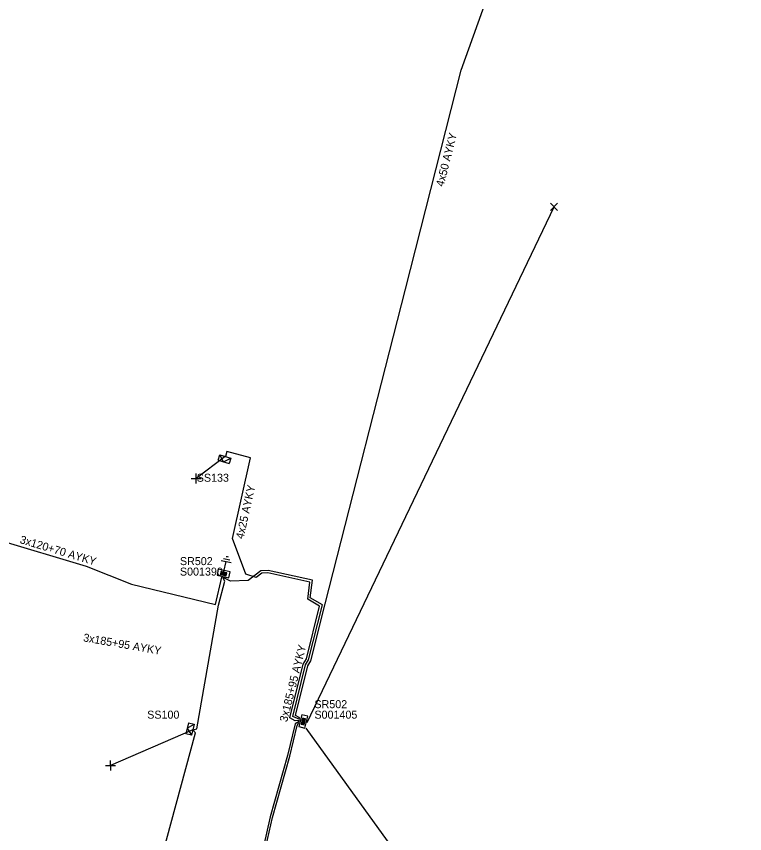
# Model space of a CAD drawing. Extents: x -762500 to -761285, y -1155006 to -1154135.
# Drawn here: x -761930.7 to -761840.3, y -1154545.1 to -1154443.6 of the extents above; entities that cross this region are included whole.
import ezdxf

# ---------------------------------------------------------------- set-up
doc = ezdxf.new("R2010")
doc.units = 0
for name, color, linetype in [('Vrstva 15', 7, 'Continuous'), ('Vrstva 28', 7, 'Continuous'), ('Vrstva 29', 7, 'Continuous'), ('Vrstva 30', 7, 'Continuous'), ('Vrstva 31', 7, 'Continuous'), ('Vrstva 33', 7, 'Continuous'), ('Vrstva 34', 7, 'Continuous'), ('Vrstva 5', 7, 'Continuous'), ('Vrstva 59', 7, 'Continuous'), ('Vrstva 6', 7, 'Continuous')]:
    doc.layers.add(name, color=color, linetype=linetype)

msp = doc.modelspace()

# ---------------------------------------------------------------- linework, layer by layer
at = {"layer": 'Vrstva 15'}
for points in [[(-761904.983, -1154510.928), (-761904.212, -1154511.091)], [(-761904.672, -1154510.672), (-761904.542, -1154510.699)], [(-761904.542, -1154510.699), (-761904.417, -1154510.726)], [(-761905.283, -1154511.181), (-761904.06, -1154511.441)], [(-761904.932, -1154512.533), (-761904.672, -1154511.311)]]:
    msp.add_lwpolyline(points, dxfattribs=at)
at = {"layer": 'Vrstva 28'}
for points in [[(-761905.64, -1154512.273), (-761905.796, -1154513.007)], [(-761905.796, -1154513.007), (-761904.329, -1154513.319)], [(-761904.173, -1154512.585), (-761905.64, -1154512.273)], [(-761905.304, -1154512.538), (-761905.383, -1154512.907)], [(-761905.383, -1154512.907), (-761904.655, -1154513.062)], [(-761905.268, -1154512.594), (-761905.327, -1154512.871)], [(-761905.327, -1154512.871), (-761904.691, -1154513.006)], [(-761904.576, -1154512.693), (-761905.304, -1154512.538)], [(-761905.231, -1154512.65), (-761905.271, -1154512.835)], [(-761905.271, -1154512.835), (-761904.728, -1154512.95)], [(-761904.632, -1154512.729), (-761905.268, -1154512.594)], [(-761904.688, -1154512.765), (-761905.231, -1154512.65)], [(-761905.195, -1154512.706), (-761905.215, -1154512.798)], [(-761905.215, -1154512.798), (-761904.764, -1154512.894)], [(-761904.744, -1154512.802), (-761905.195, -1154512.706)], [(-761904.795, -1154512.839), (-761905.164, -1154512.761)], [(-761904.764, -1154512.894), (-761904.744, -1154512.802)], [(-761904.728, -1154512.95), (-761904.688, -1154512.765)], [(-761904.691, -1154513.006), (-761904.632, -1154512.729)], [(-761904.655, -1154513.062), (-761904.576, -1154512.693)], [(-761904.329, -1154513.319), (-761904.173, -1154512.585)], [(-761895.272, -1154530.34), (-761895.635, -1154531.795)], [(-761895.187, -1154530.756), (-761895.367, -1154531.479)], [(-761895.152, -1154530.814), (-761895.31, -1154531.444)], [(-761894.544, -1154530.521), (-761895.272, -1154530.34)], [(-761895.118, -1154530.871), (-761895.252, -1154531.41)], [(-761895.084, -1154530.928), (-761895.195, -1154531.375)], [(-761894.82, -1154530.848), (-761895.187, -1154530.756)], [(-761894.877, -1154530.882), (-761895.152, -1154530.814)], [(-761895.139, -1154531.347), (-761895.048, -1154530.98)], [(-761894.935, -1154530.917), (-761895.118, -1154530.871)], [(-761895.103, -1154531.398), (-761894.992, -1154530.951)], [(-761894.992, -1154530.951), (-761895.084, -1154530.928)], [(-761895.069, -1154531.455), (-761894.935, -1154530.917)], [(-761895.035, -1154531.513), (-761894.877, -1154530.882)], [(-761895, -1154531.57), (-761894.82, -1154530.848)], [(-761894.907, -1154531.977), (-761894.544, -1154530.521)], [(-761895.635, -1154531.795), (-761894.907, -1154531.977)], [(-761895.367, -1154531.479), (-761895, -1154531.57)], [(-761895.31, -1154531.444), (-761895.035, -1154531.513)], [(-761895.252, -1154531.41), (-761895.069, -1154531.455)], [(-761895.195, -1154531.375), (-761895.103, -1154531.398)]]:
    msp.add_lwpolyline(points, dxfattribs=at)
at = {"layer": 'Vrstva 31'}
for points in [[(-761905.647, -1154498.735), (-761905.442, -1154498.065), (-761904.104, -1154498.475), (-761904.308, -1154499.144)], [(-761905.647, -1154498.735), (-761904.308, -1154499.144)], [(-761904.978, -1154498.939), (-761905.442, -1154498.065)], [(-761904.978, -1154498.939), (-761904.104, -1154498.475)], [(-761909.319, -1154531.329), (-761909.658, -1154532.687)], [(-761909.319, -1154531.329), (-761908.64, -1154531.498), (-761908.979, -1154532.856), (-761909.658, -1154532.687)], [(-761909.488, -1154532.008), (-761908.64, -1154531.498)], [(-761909.488, -1154532.008), (-761908.979, -1154532.856)]]:
    msp.add_lwpolyline(points, dxfattribs=at)
at = {"layer": 'Vrstva 34'}
for points in [[(-761864.422, -1154466.828), (-761863.538, -1154467.712)], [(-761864.422, -1154467.712), (-761863.538, -1154466.828)], [(-761908.369, -1154501.625), (-761908.391, -1154500.375)], [(-761909.005, -1154501.011), (-761907.755, -1154500.989)], [(-761918.989, -1154537.255), (-761919.011, -1154536.005)], [(-761919.625, -1154536.641), (-761918.375, -1154536.619)]]:
    msp.add_lwpolyline(points, dxfattribs=at)
at = {"layer": 'Vrstva 5'}
for points in [[(-761895.51, -1154530.78), (-761895.62, -1154530.65), (-761896.05, -1154530.41), (-761894.54, -1154524.27), (-761894.15, -1154523.62), (-761892.39, -1154516.56), (-761882.4, -1154477.51), (-761875.49, -1154450.3), (-761869.77, -1154434.24), (-761865.39, -1154418.93), (-761865.76, -1154418.41)], [(-761895.58, -1154531.04), (-761896.1, -1154531.08), (-761896.75, -1154530.71), (-761895.1, -1154524.03), (-761894.71, -1154523.38), (-761893.08, -1154516.84), (-761894.54, -1154515.98), (-761894.27, -1154513.86), (-761899.48, -1154512.72), (-761900.25, -1154512.76), (-761900.93, -1154513.29), (-761902.22, -1154512.86), (-761903.88, -1154508.44), (-761901.65, -1154498.42), (-761904.56, -1154497.64), (-761904.76, -1154498.27)], [(-761960.09, -1154505.71), (-761959.91, -1154505.69), (-761959.62, -1154505.22), (-761950.8, -1154509.6), (-761942.84, -1154513.23), (-761936.78, -1154516.16), (-761933.1, -1154508.56), (-761922.02, -1154511.87), (-761916.39, -1154514.1), (-761906, -1154516.65), (-761905.22, -1154513.26)], [(-761895.54, -1154530.91), (-761896.4, -1154530.56), (-761894.82, -1154524.15), (-761894.43, -1154523.5), (-761892.73, -1154516.7), (-761894.22, -1154515.82), (-761893.94, -1154513.62), (-761899.46, -1154512.42), (-761900.36, -1154512.47), (-761901.92, -1154513.68), (-761904.12, -1154513.74), (-761904.96, -1154513.32)], [(-761908.81, -1154532.18), (-761908.31, -1154532.07), (-761905.63, -1154516.74), (-761904.84, -1154513.76), (-761905.09, -1154513.29)], [(-761895.61, -1154531.16), (-761896.11, -1154531.47), (-761897.05, -1154535.37), (-761899.2, -1154543), (-761900.01, -1154546.67), (-761906.12, -1154570.94), (-761903.36, -1154575.51), (-761908.56, -1154592.81), (-761901.89, -1154594.56), (-761874.94, -1154633.46), (-761874.08, -1154634.63), (-761862.51, -1154631.88), (-761850.03, -1154626), (-761847.78, -1154629.75), (-761844.92, -1154635.82), (-761841.98, -1154640.25), (-761841.84, -1154640.14)], [(-761905.14, -1154568.82), (-761905.24, -1154568.67), (-761899.72, -1154546.74), (-761898.91, -1154543.07), (-761896.76, -1154535.45), (-761895.85, -1154531.66), (-761895.64, -1154531.29)], [(-761919.23, -1154555.21), (-761919.07, -1154555.86), (-761914.99, -1154556.7), (-761908.46, -1154532.58), (-761908.81, -1154532.18)], [(-761894.78, -1154532), (-761840.33, -1154607.44), (-761840.36, -1154607.67)]]:
    msp.add_lwpolyline(points, dxfattribs=at)
at = {"layer": 'Vrstva 59'}
for points in [[(-761894.6, -1154531.29), (-761863.98, -1154467.27)], [(-761904.77, -1154498.27), (-761908.38, -1154501)], [(-761908.81, -1154532.18), (-761919, -1154536.63)]]:
    msp.add_lwpolyline(points, dxfattribs=at)

# ---------------------------------------------------------------- texts
at = {"layer": 'Vrstva 29'}
for s, p in [('S001390', (-761910.4, -1154513.05)), ('S001405', (-761893.71, -1154530.81))]:
    msp.add_text(s, height=0.9943, dxfattribs=at).set_placement(p)
at = {"layer": 'Vrstva 30'}
for p in [(-761910.4, -1154511.75), (-761893.71, -1154529.51)]:
    msp.add_text('SR502', height=0.9943, dxfattribs=at).set_placement(p)
at = {"layer": 'Vrstva 33'}
for s, p in [('SS133', (-761908.31, -1154501.4)), ('SS100', (-761914.46, -1154530.81))]:
    msp.add_text(s, height=0.9943, dxfattribs=at).set_placement(p)
at = {"layer": 'Vrstva 6'}
for s, height, rotation, p in [('4x50 AYKY', 0.9943, 75.75832, (-761877.69, -1154464.83)), ('4x25 AYKY', 0.9943, 77.43849, (-761902.52, -1154508.57)), ('3x120+70 AYKY', 0.99428, 343.3672, (-761930.34, -1154509)), ('3x185+95 AYKY', 0.99428, 350.07901, (-761922.46, -1154521.2)), ('3x185+95 AYKY', 0.99429, 75.96376, (-761897.1, -1154531.29))]:
    msp.add_text(s, height=height, rotation=rotation, dxfattribs=at).set_placement(p)

doc.saveas('drawing.dxf')
